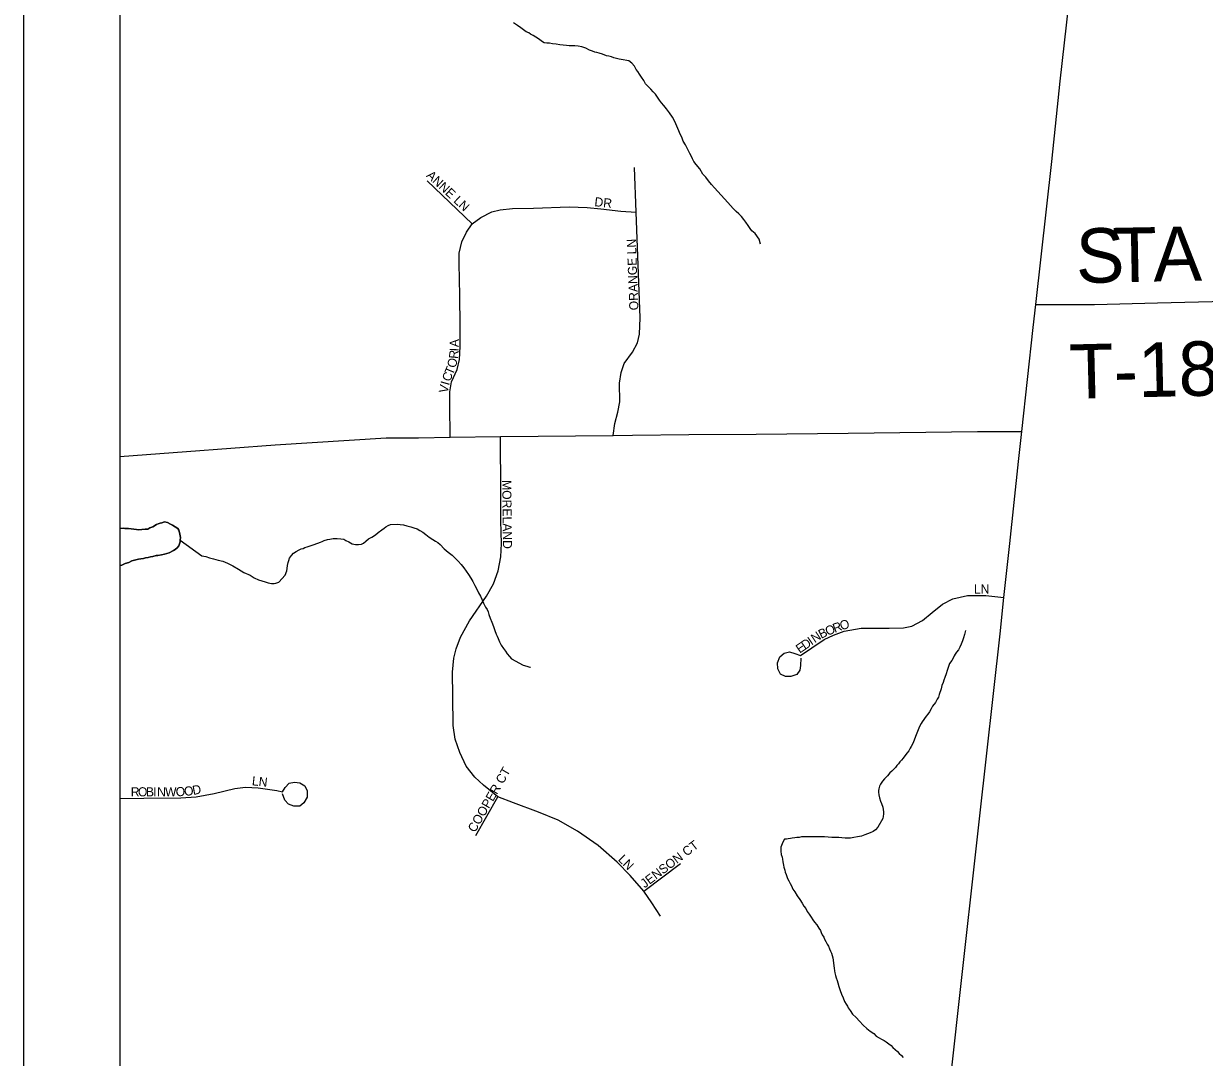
# Model space of a CAD drawing. Extents: x 0 to 34, y 0 to 22.
# Drawn here: x 2.262 to 3.494, y 18.059 to 19.138 of the extents above; entities that cross this region are included whole.
import ezdxf

# ---------------------------------------------------------------- set-up
doc = ezdxf.new("R2010")
doc.units = 0
for name, color, linetype in [('GM_X_County', 7, 'Continuous'), ('GM_X_Minor_Lake', 7, 'Continuous'), ('GM_X_Minor_River', 7, 'Continuous'), ('GM_X_State_Route', 7, 'Continuous'), ('GM_X_Township', 7, 'Continuous'), ('GM_X_Township_Road', 7, 'Continuous'), ('GM_X_Township_Road_Text', 7, 'Continuous'), ('GM_X_Township_Subdivision', 7, 'Continuous'), ('GM_X_Township_Subdivision_Text', 7, 'Continuous'), ('SH_Data', 7, 'Continuous')]:
    doc.layers.add(name, color=color, linetype=linetype)

msp = doc.modelspace()

# ---------------------------------------------------------------- linework, layer by layer
at = {"layer": 'GM_X_County'}
msp.add_lwpolyline([(9.1622, 14.342), (9.1622, 21.1385), (2.3622, 21.1385), (2.3622, 14.3385), (9.0003, 14.3385)], dxfattribs=at)
at = {"layer": 'GM_X_Minor_Lake'}
for points in [[(2.4251, 18.5988), (2.4254, 18.6015), (2.4246, 18.6068), (2.4237, 18.6091), (2.4226, 18.6109), (2.4199, 18.6128), (2.4172, 18.6146), (2.4152, 18.6153), (2.4118, 18.6172), (2.4087, 18.6179), (2.4061, 18.617), (2.4042, 18.6166), (2.4023, 18.6158), (2.4004, 18.615), (2.3967, 18.6127), (2.3936, 18.6115), (2.3914, 18.6103), (2.3887, 18.6102), (2.3853, 18.6098), (2.3815, 18.6097), (2.3796, 18.61), (2.3712, 18.611), (2.3674, 18.6109), (2.3655, 18.6112), (2.3628, 18.6108), (2.3622, 18.6107)], [(2.3622, 18.6107), (2.3628, 18.6108), (2.3655, 18.6112), (2.3674, 18.6109), (2.3712, 18.611), (2.3796, 18.61), (2.3815, 18.6097), (2.3853, 18.6098), (2.3887, 18.6102), (2.3914, 18.6103), (2.3936, 18.6115), (2.3967, 18.6127), (2.4004, 18.615), (2.4023, 18.6158), (2.4042, 18.6166), (2.4061, 18.617), (2.4087, 18.6179), (2.4118, 18.6172), (2.4152, 18.6153), (2.4172, 18.6146), (2.4199, 18.6128), (2.4226, 18.6109), (2.4237, 18.6091), (2.4246, 18.6068), (2.4254, 18.6015), (2.4251, 18.5988), (2.4251, 18.5969), (2.4237, 18.5927), (2.4219, 18.5908), (2.42, 18.5892), (2.4181, 18.588), (2.4136, 18.5857), (2.4113, 18.5849), (2.4087, 18.584), (2.4057, 18.5836), (2.4019, 18.5827), (2.4, 18.5827), (2.3966, 18.5819), (2.3943, 18.5814), (2.3916, 18.5806), (2.389, 18.5802), (2.3867, 18.5798), (2.3841, 18.5793), (2.3818, 18.5789), (2.3788, 18.5781), (2.3746, 18.5772), (2.3716, 18.5756), (2.3678, 18.5744), (2.3644, 18.5728), (2.3622, 18.5722)], [(2.3622, 18.5722), (2.3644, 18.5728), (2.3678, 18.5744), (2.3716, 18.5756), (2.3746, 18.5772), (2.3788, 18.5781), (2.3818, 18.5789), (2.3841, 18.5793), (2.3867, 18.5798), (2.389, 18.5802), (2.3916, 18.5806), (2.3943, 18.5814), (2.3966, 18.5819), (2.4, 18.5827), (2.4019, 18.5827), (2.4057, 18.5836), (2.4087, 18.584), (2.4113, 18.5849), (2.4136, 18.5857), (2.4181, 18.588), (2.42, 18.5892), (2.4219, 18.5908), (2.4237, 18.5927), (2.4251, 18.5969), (2.4251, 18.5988)]]:
    msp.add_lwpolyline(points, dxfattribs=at)
at = {"layer": 'GM_X_Minor_River'}
for points in [[(3.031, 18.9077), (3.0293, 18.9129), (3.0254, 18.9186), (3.0219, 18.9215), (3.02, 18.9241), (3.018, 18.9271), (3.0157, 18.9305), (3.0133, 18.9335), (3.011, 18.9365), (3.0082, 18.9391), (3.0055, 18.9417), (3.0024, 18.9447), (2.9997, 18.948), (2.9966, 18.951), (2.9864, 18.9626), (2.9829, 18.9663), (2.9798, 18.97), (2.9767, 18.9737), (2.9739, 18.9775), (2.9708, 18.9808), (2.9677, 18.9861), (2.9638, 18.9906), (2.9614, 18.9939), (2.9598, 18.9966), (2.9587, 18.9992), (2.9571, 19.0022), (2.9551, 19.0063), (2.9527, 19.0112), (2.9503, 19.015), (2.9487, 19.0191), (2.9471, 19.0225), (2.9455, 19.0259), (2.9435, 19.0308), (2.9415, 19.0357), (2.9391, 19.0402), (2.936, 19.0447), (2.9329, 19.0488), (2.9301, 19.0522), (2.9274, 19.0551), (2.9254, 19.0578), (2.9235, 19.0611), (2.9211, 19.0641), (2.9188, 19.0664), (2.9165, 19.0693), (2.9133, 19.0723), (2.911, 19.0749), (2.909, 19.0783), (2.9067, 19.0817), (2.9047, 19.085), (2.9027, 19.0877), (2.9012, 19.0899), (2.8992, 19.0933), (2.8965, 19.0963), (2.8934, 19.0989), (2.8915, 19.0992), (2.8876, 19.0999), (2.8854, 19.1002), (2.8835, 19.1005), (2.8804, 19.1012), (2.8777, 19.1019), (2.8754, 19.103), (2.8724, 19.1037), (2.8701, 19.1041), (2.8658, 19.1059), (2.8624, 19.1069), (2.8601, 19.1076), (2.8578, 19.108), (2.8555, 19.1091), (2.8524, 19.1101), (2.8486, 19.112), (2.8444, 19.1134), (2.8406, 19.1141), (2.8371, 19.1144), (2.8345, 19.1147), (2.831, 19.1146), (2.8284, 19.1149), (2.8249, 19.1152), (2.8215, 19.1155), (2.8177, 19.1162), (2.8139, 19.1165), (2.8108, 19.1172), (2.8078, 19.1175), (2.8051, 19.1178), (2.8024, 19.1193), (2.8001, 19.1212), (2.7962, 19.1237), (2.7935, 19.1252), (2.7908, 19.1267), (2.7889, 19.1281), (2.7862, 19.1292), (2.7835, 19.1314), (2.7808, 19.1333), (2.7773, 19.1359), (2.7731, 19.1384)], [(2.4251, 18.5988), (2.4479, 18.5826), (2.4521, 18.5816), (2.4556, 18.5805), (2.4598, 18.5794), (2.4647, 18.578), (2.4697, 18.577), (2.4747, 18.5748), (2.4801, 18.5719), (2.4859, 18.5686), (2.4916, 18.5649), (2.4982, 18.5624), (2.5024, 18.5595), (2.507, 18.5573), (2.5105, 18.5562), (2.5139, 18.5552), (2.517, 18.5541), (2.5204, 18.5534), (2.5231, 18.5535), (2.525, 18.5539), (2.528, 18.5551), (2.5347, 18.5621), (2.5365, 18.5667), (2.5368, 18.5693), (2.5371, 18.5724), (2.5378, 18.5754), (2.5385, 18.5777), (2.5393, 18.58), (2.5415, 18.5827), (2.5433, 18.5851), (2.5463, 18.587), (2.5493, 18.5886), (2.5516, 18.5898), (2.5535, 18.5902), (2.5554, 18.591), (2.5576, 18.5918), (2.5607, 18.5927), (2.5641, 18.5939), (2.569, 18.5955), (2.5716, 18.5967), (2.5735, 18.5975), (2.5754, 18.5983), (2.5788, 18.5995), (2.5814, 18.5999), (2.5848, 18.6004), (2.589, 18.6005), (2.5928, 18.6002), (2.5959, 18.5999), (2.5982, 18.5984), (2.6013, 18.597), (2.6047, 18.5951), (2.6082, 18.5944), (2.6112, 18.5941), (2.6143, 18.5946), (2.6165, 18.5958), (2.6191, 18.5977), (2.6218, 18.6001), (2.6251, 18.602), (2.6289, 18.6044), (2.6319, 18.6067), (2.6356, 18.6095), (2.6379, 18.6114), (2.6397, 18.6126), (2.6424, 18.6142), (2.6446, 18.615), (2.6519, 18.6155), (2.6549, 18.6152), (2.6583, 18.6149), (2.6618, 18.6139), (2.666, 18.6128), (2.6691, 18.6117), (2.6725, 18.6107), (2.6752, 18.6088), (2.6783, 18.607), (2.6814, 18.6048), (2.6849, 18.6018), (2.6887, 18.5996), (2.6918, 18.5978), (2.6941, 18.5963), (2.6964, 18.5941), (2.7007, 18.5896), (2.705, 18.5863), (2.7092, 18.583), (2.7123, 18.58), (2.7154, 18.577), (2.7186, 18.5733), (2.7213, 18.5699), (2.7237, 18.5666), (2.726, 18.5628), (2.7284, 18.5591), (2.7307, 18.5557), (2.7327, 18.5516), (2.7347, 18.5478), (2.7367, 18.5437), (2.7387, 18.5403), (2.7399, 18.5373), (2.7419, 18.5331), (2.7439, 18.529)], [(2.7439, 18.529), (2.7454, 18.5264), (2.7466, 18.5241), (2.7474, 18.5211), (2.7487, 18.5173), (2.7503, 18.5132), (2.7523, 18.5087), (2.7535, 18.5045), (2.7551, 18.5007), (2.7559, 18.4985), (2.7571, 18.4962), (2.7583, 18.4928), (2.7603, 18.4891), (2.7627, 18.4857), (2.7646, 18.4831), (2.7666, 18.4801), (2.7689, 18.4775), (2.7709, 18.4749), (2.7832, 18.4683), (2.787, 18.4672), (2.7901, 18.4661), (2.7908, 18.4662)], [(3.245, 18.5045), (3.2439, 18.5003), (3.2429, 18.4969), (3.2418, 18.4938), (3.2403, 18.4904), (3.2389, 18.4873), (3.2374, 18.4842), (3.2356, 18.4819), (3.2341, 18.48), (3.233, 18.4781), (3.2319, 18.4757), (3.2304, 18.4734), (3.2282, 18.47), (3.2268, 18.4658), (3.2257, 18.4627), (3.2247, 18.4592), (3.2232, 18.4554), (3.2221, 18.4527), (3.2214, 18.4504), (3.22, 18.447), (3.2193, 18.4436), (3.2186, 18.4416), (3.2182, 18.4397), (3.2175, 18.4378), (3.2168, 18.4348), (3.2153, 18.4328), (3.2135, 18.4294), (3.2105, 18.4255), (3.2091, 18.4228), (3.2072, 18.4197), (3.2054, 18.4174), (3.2039, 18.4151), (3.1995, 18.4093), (3.1984, 18.4074), (3.1969, 18.4043), (3.1955, 18.4009), (3.194, 18.3974), (3.1926, 18.3939), (3.1911, 18.3901), (3.1897, 18.3867), (3.1882, 18.3836), (3.1871, 18.3817), (3.1857, 18.379), (3.1838, 18.377), (3.1816, 18.3736), (3.1797, 18.3712), (3.1779, 18.3693), (3.1764, 18.3674), (3.1749, 18.3654), (3.1731, 18.3635), (3.1716, 18.3616), (3.1679, 18.3577), (3.166, 18.3561), (3.1634, 18.353), (3.1604, 18.3499), (3.1582, 18.3472), (3.156, 18.3441), (3.1552, 18.3422), (3.1545, 18.3395), (3.1542, 18.3376), (3.1539, 18.3357), (3.1543, 18.3331), (3.1551, 18.33), (3.156, 18.3266), (3.1572, 18.324), (3.1584, 18.3202), (3.1588, 18.3176), (3.1592, 18.3153), (3.1593, 18.3134), (3.159, 18.3104), (3.1586, 18.3085), (3.1535, 18.2992), (3.1509, 18.2965), (3.1483, 18.2949), (3.1453, 18.2933), (3.1426, 18.2925), (3.1396, 18.2913), (3.1362, 18.2901), (3.132, 18.2893), (3.1282, 18.2884), (3.1248, 18.288), (3.1218, 18.2879), (3.1191, 18.2878), (3.1157, 18.2881), (3.1126, 18.2885), (3.1088, 18.2884), (3.1054, 18.2887), (3.1016, 18.289), (3.0978, 18.2893), (3.0948, 18.2892), (3.0913, 18.2891), (3.0875, 18.2891), (3.0841, 18.2894), (3.0811, 18.2893), (3.0792, 18.2893), (3.0773, 18.2892), (3.0738, 18.2891), (3.0712, 18.2887), (3.0689, 18.2886), (3.0666, 18.2882), (3.064, 18.2878)], [(3.064, 18.2878), (3.0621, 18.2874), (3.0598, 18.2873), (3.0579, 18.2869), (3.056, 18.2868), (3.0545, 18.2845), (3.0534, 18.2819), (3.052, 18.2784), (3.0521, 18.2742), (3.0525, 18.2708), (3.0534, 18.2682), (3.0538, 18.2659), (3.0542, 18.2632), (3.0547, 18.2598), (3.0551, 18.2576), (3.0563, 18.2546), (3.0567, 18.2523), (3.0575, 18.25), (3.0584, 18.2478), (3.0592, 18.2459), (3.0604, 18.2432), (3.0619, 18.2406), (3.0631, 18.238), (3.0647, 18.2346), (3.0667, 18.232), (3.0691, 18.2278), (3.0718, 18.2237), (3.0742, 18.22), (3.0761, 18.217), (3.0781, 18.2144), (3.0797, 18.2114), (3.0816, 18.2084), (3.0836, 18.2054), (3.0856, 18.2027), (3.0871, 18.2001), (3.0895, 18.1975), (3.0907, 18.1956), (3.0918, 18.1938), (3.0934, 18.1915), (3.0942, 18.1896), (3.0954, 18.187), (3.097, 18.1847), (3.0978, 18.1825), (3.099, 18.1799), (3.1006, 18.1772), (3.1017, 18.175), (3.1029, 18.1723), (3.1041, 18.1701), (3.1049, 18.1678), (3.1058, 18.1656), (3.1062, 18.1629), (3.1076, 18.1523), (3.108, 18.1496), (3.1084, 18.1474), (3.1092, 18.1447), (3.1097, 18.1421), (3.1109, 18.1394), (3.1117, 18.1368), (3.1125, 18.133), (3.1141, 18.1289), (3.1154, 18.1251), (3.117, 18.1213), (3.1186, 18.1176), (3.1202, 18.1146), (3.1217, 18.1127), (3.1225, 18.1108), (3.1245, 18.1082), (3.1268, 18.1041), (3.1307, 18.1007), (3.1342, 18.097), (3.1381, 18.0929), (3.142, 18.0892), (3.1455, 18.0866), (3.149, 18.084), (3.1517, 18.0814), (3.1548, 18.0796), (3.1571, 18.0781), (3.1598, 18.0767), (3.1621, 18.0752), (3.1648, 18.0734), (3.1671, 18.0715), (3.1691, 18.0693), (3.1714, 18.0674), (3.1737, 18.0652), (3.1756, 18.0633), (3.178, 18.0611), (3.1799, 18.0589)]]:
    msp.add_lwpolyline(points, dxfattribs=at)
at = {"layer": 'GM_X_State_Route'}
msp.add_lwpolyline([(3.2158, 17.9155), (3.2372, 18.1079), (3.2598, 18.311), (3.2809, 18.5009), (3.285, 18.539), (3.2912, 18.5952), (3.3003, 18.6807), (3.3036, 18.7121), (3.3155, 18.8208), (3.3183, 18.8446), (3.3349, 18.9937), (3.3437, 19.0776), (3.3548, 19.1765)], dxfattribs=at)
at = {"layer": 'GM_X_Township'}
msp.add_lwpolyline([(2.3622, 19.6335), (2.3622, 14.3385), (4.4492, 14.3385)], dxfattribs=at)
at = {"layer": 'GM_X_Township_Road'}
for points in [[(3.3183, 18.8446), (3.3794, 18.8448), (3.4451, 18.8463), (3.5735, 18.8497), (3.6432, 18.8505), (3.7163, 18.8512), (3.8701, 18.8532), (3.983, 18.8554), (4.1191, 18.8574), (4.2011, 18.8586), (4.2441, 18.8588), (4.2875, 18.8601), (4.3307, 18.8604), (4.3653, 18.8614), (4.4041, 18.8614), (4.4288, 18.8614)], [(2.3622, 18.6859), (2.4318, 18.6912), (2.5244, 18.6981), (2.6017, 18.703), (2.6403, 18.7055), (2.674, 18.7056), (2.7069, 18.7061), (2.7595, 18.7071), (2.8771, 18.708), (2.8973, 18.7085), (2.9561, 18.709), (3.0263, 18.7094), (3.1225, 18.7104), (3.2574, 18.7123), (3.3036, 18.7121)]]:
    msp.add_lwpolyline(points, dxfattribs=at)
at = {"layer": 'GM_X_Township_Subdivision'}
for points in [[(2.8771, 18.708), (2.8788, 18.7206), (2.8819, 18.7323), (2.8842, 18.7432), (2.8838, 18.7625), (2.8854, 18.7737), (2.8885, 18.783), (2.8973, 18.7951), (2.9026, 18.8046), (2.9047, 18.8137), (2.9054, 18.8306), (2.9011, 18.941), (2.8992, 18.9877)], [(2.73, 18.9289), (2.6829, 18.9736)], [(2.7069, 18.7061), (2.7065, 18.7397), (2.7065, 18.7535), (2.7084, 18.764), (2.7141, 18.777), (2.7167, 18.7873), (2.7174, 18.8008), (2.7174, 18.8223), (2.7169, 18.8542), (2.7162, 18.8875), (2.7165, 18.8982), (2.7193, 18.9101), (2.7241, 18.9203), (2.73, 18.9289), (2.7388, 18.9355), (2.7505, 18.9415), (2.7593, 18.9436), (2.7721, 18.9448), (2.794, 18.9453), (2.8312, 18.9467), (2.85, 18.9458), (2.8642, 18.9446), (2.885, 18.942), (2.9011, 18.941)], [(2.9266, 18.2066), (2.9173, 18.2204), (2.9092, 18.2327), (2.8947, 18.2489), (2.8814, 18.2627), (2.8616, 18.2801), (2.8397, 18.2951), (2.8197, 18.3065), (2.7993, 18.3151), (2.7729, 18.3246), (2.7567, 18.331), (2.7419, 18.3432), (2.7326, 18.3515), (2.7238, 18.3629), (2.7172, 18.3772), (2.7122, 18.391), (2.71, 18.4053), (2.7098, 18.4358), (2.7095, 18.461), (2.7107, 18.4755), (2.7131, 18.4855), (2.7176, 18.4976), (2.7272, 18.5145), (2.745, 18.5402), (2.7522, 18.5531), (2.7569, 18.5669), (2.7598, 18.5814), (2.7605, 18.5954), (2.7598, 18.6188), (2.7598, 18.649), (2.7595, 18.7071)], [(3.073, 18.4757), (3.0727, 18.4681), (3.0718, 18.4631), (3.0687, 18.4586), (3.0625, 18.4565), (3.0568, 18.4565), (3.0518, 18.4591), (3.0489, 18.4646), (3.0485, 18.4707), (3.0511, 18.4769), (3.0556, 18.481), (3.0613, 18.4822), (3.0668, 18.4805), (3.0725, 18.4784), (3.0846, 18.4864), (3.0972, 18.4953), (3.1072, 18.4998), (3.1182, 18.5038), (3.136, 18.5069), (3.1651, 18.5069), (3.1801, 18.5074), (3.1889, 18.5091), (3.2001, 18.515), (3.2101, 18.5233), (3.221, 18.5319), (3.2315, 18.5376), (3.2469, 18.5409), (3.2662, 18.5412), (3.285, 18.539)], [(2.3622, 18.3294), (2.3872, 18.3296), (2.4258, 18.3298), (2.4417, 18.3311), (2.4605, 18.3346), (2.4823, 18.3398), (2.4932, 18.3412), (2.5064, 18.3405), (2.5261, 18.3375), (2.5318, 18.3363), (2.5348, 18.3407), (2.5388, 18.3452), (2.5445, 18.3464), (2.5502, 18.3457), (2.5554, 18.3425), (2.5578, 18.3373), (2.5576, 18.3306), (2.5541, 18.3246), (2.5499, 18.3214), (2.5437, 18.3212), (2.5383, 18.3234), (2.5343, 18.3274), (2.5318, 18.3341)], [(2.7336, 18.2908), (2.7567, 18.331)], [(2.9092, 18.2327), (2.9475, 18.2613)]]:
    msp.add_lwpolyline(points, dxfattribs=at)
at = {"layer": 'SH_Data'}
msp.add_line((2.2617, 21.2383), (2.2617, 14.2383), dxfattribs=at)

# ---------------------------------------------------------------- texts
at = {"layer": 'GM_X_Township_Road_Text'}
for s, height, rotation, p in [('S', 0.0568, 1.0787, (3.3605, 18.867)), ('T', 0.0568, 1.0758, (3.3988, 18.8678)), ('A', 0.0568, 1.0796, (3.4413, 18.8686)), ('T-187', 0.05682, 1.3983, (3.3538, 18.7461))]:
    msp.add_text(s, height=height, rotation=rotation, dxfattribs=at).set_placement(p)
at = {"layer": 'GM_X_Township_Subdivision_Text'}
for s, rotation, p in [('ANNE LN', 316.9739, (2.6815, 18.9785)), ('DR', 353.9994, (2.8572, 18.9473)), ('ORANGE LN', 92.1492, (2.9035, 18.8388)), ('A', 89.2495, (2.7159, 18.8001)), ('R', 84.8168, (2.715, 18.7877)), ('I', 87.2504, (2.7157, 18.7956)), ('O', 75.3171, (2.7126, 18.7779)), ('C', 68.5684, (2.7068, 18.7635)), ('T', 67.4831, (2.7095, 18.7704)), ('V', 79.4703, (2.7043, 18.7517)), ('I', 74.0126, (2.7058, 18.7597)), ('MORELAND', 270.7179, (2.7612, 18.6614)), ('LN', 0, (3.2536, 18.5431)), ('R', 21.2241, (3.1084, 18.502)), ('O', 16.5339, (3.1152, 18.5047)), ('N', 33.9568, (3.0875, 18.4912)), ('B', 26.4782, (3.0942, 18.4957)), ('O', 21.9475, (3.1007, 18.4989)), ('E', 34.4705, (3.0718, 18.4803)), ('D', 34.4736, (3.0773, 18.4841)), ('I', 34.4689, (3.0841, 18.4888)), ('LN', 353.9964, (2.4997, 18.3431)), ('COOPER CT', 60.0679, (2.7329, 18.2931)), ('R', 0.0243, (2.3736, 18.3315)), ('O', 0.0219, (2.3811, 18.3315)), ('B', 0.0178, (2.3894, 18.3315)), ('I', 0.0309, (2.3969, 18.3315)), ('N', 0.0219, (2.4011, 18.3315)), ('W', 0.0288, (2.4094, 18.3315)), ('O', 2.6204, (2.4207, 18.3315)), ('O', 6.0848, (2.4297, 18.3319)), ('D', 10.719, (2.4388, 18.3329)), ('JENSON CT', 37.1869, (2.91, 18.2353)), ('LN', 315, (2.8815, 18.2651))]:
    msp.add_text(s, height=0.00947, rotation=rotation, dxfattribs=at).set_placement(p)

doc.saveas('drawing.dxf')
